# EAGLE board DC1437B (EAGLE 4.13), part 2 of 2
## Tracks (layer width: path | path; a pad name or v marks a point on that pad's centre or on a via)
+2.5V
  Bottom 0.203: 47.24,50.55 47.12,50.42 R9.2 47.75,50.42 | 45.85,49.28 C44.1 47.75,49.28 47.88,49.4
  Bottom 0.254: 47.24,51.94 U10.3
  Bottom 0.813: R13.1 30.8,38.67 30.86,38.74 R14.1 40.83,38.67 41.53,39.37 41.53,46.23 43.31,48.01 47.75,48.01 48.13,48.39 48.13,49.4 48.51,49.78
  pour Bottom (no thermals): 47.17,52.02 51.31,52.02 51.31,49.15 51.05,48.9 47.88,48.9 47.62,49.15 47.62,51 47.5,51.13 47.17,51.13
+3.3V  (via drill 0.38)
  Top 0.254: 47.11,39.11 47.12,39.12 | 51.98,44.61 51.94,44.58 51.94,44.07 51.99,44.11 | 51.94,33.66 51.99,33.61 51.99,33.19 51.94,33.15 51.98,33.11
  Top 0.305: U3.12 47.11,39.11 | 51.98,44.61 U3.48 | 51.99,44.11 U3.47 | 51.99,33.61 U3.26 | 51.98,33.11 U3.25 | U4.48 51.98,27.09 51.94,27.05 51.94,26.67 52.03,26.59 U4.47 | U4.12 47.11,21.59 47.12,21.59 | U4.25 51.98,15.59 51.94,15.62 51.94,16.13 51.99,16.09 U4.26
  Route2 0.61: v49.53,38.1 v49.53,39.62 | v49.53,20.57 v49.53,22.1
  Route3 0.61: v49.53,38.1 v49.53,39.62 | v49.53,20.57 v49.53,22.1
  Bottom 0.203: R29.2 53.21,16.89 v49.53,20.57 | R12.2 47.12,56.01 47.24,55.88 U10.10
  Bottom 0.61: TP3.1 43.31,57.28 47.37,57.28 | 47.37,57.28 47.5,57.28 | v49.53,20.57 v49.53,21.34 v49.53,22.1 v49.53,38.1 v49.53,38.86 v49.53,39.62 49.53,47.62 49.91,48.01 51.56,48.01 51.94,48.39 51.94,56.64 51.31,57.28 47.37,57.28
  Bottom 0.813: TP3.1 40.64,54.74 38.67,52.77 C5.1 38.74,51.44 38.74,49.34 R3.1 37.02,49.34 36.77,49.08 R16.1
  pour Top (no thermals): 52.07,46.23 52.07,31.5 46.99,31.5 46.99,46.23
  pour Top (isolate 0.254, no thermals): 46.99,28.7 46.99,13.97 52.07,13.97 52.07,28.7
  pour Bottom (no thermals): 47.8,54.41 47.8,57.51 47.32,57.51 47.04,57.51 47.04,55.68 47.04,55.17 47.14,55.07 47.19,55.02 47.19,54.41
+5V
  Bottom 0.813: TP5.1 31.05,52.77 C6.1 30.99,51.44 30.99,49.66 31.62,49.02 R15.1
AMP_EN
  Top 0.152: U2.C3 20.95,27.3 20.95,17.14 20.57,16.76 15.62,16.76 15.24,16.38 10.06,16.38 9.8,16.13 9.8,15.11 8.66,13.97 7.48,13.97 J6.4
ECCN  (via drill 0.25)
  Top 0.305: v33.91,30.1 R41.1 32.13,30.1 U2.E12
  Bottom 0.305: R4.2 35.62,17.34 35.31,17.65 35.31,29.34 34.67,29.97 34.04,29.97 v33.91,30.1
ENCP  (via drill 0.25)
  Top 0.305: v33.53,29.46 33.15,29.46 33.02,29.59 R41.2 32.13,29.59 U2.D12
  Bottom 0.305: R5.2 34.48,17.34 34.8,17.65 34.8,29.08 34.42,29.46 v33.53,29.46
EXT_REF
  Bottom 0.254: J4.5 13.99,11.32 13.97,11.3 TP1.1
GND  (via drill 0.3, 0.38, 0.81, 4.78)
  Top 0.127: U2.H10 29.21,33.91 29.84,33.27 29.84,33.02 | U2.H8 27,33.96 27.41,33.96 27.74,33.63 28.17,33.63 28.57,33.22 v28.57,31.75
  Top 0.152: v29.84,31.75 29.84,33.02
  Top 0.254: v35.94,45.59 34.93,45.59 | v35.94,45.59 36.83,45.59 | v35.94,45.59 35.94,46.48 | v35.94,44.32 v35.94,45.59 | 26.29,20.32 v27.3,20.32 | v27.3,20.32 28.19,20.32 | v27.3,20.32 27.3,21.34 | v27.3,20.32 27.3,19.3
  Top 0.305: U3.27 54.79,34.11 v55.12,33.91 | U3.23 44.53,33.61 | 44.53,33.61 44.45,33.53 | 44.53,33.61 44.53,33.99 44.65,34.11 U3.22 | U3.1 44.49,44.61 44.45,44.58 44.45,44.2 44.53,44.11 | U3.2 44.53,44.11 | 44.53,44.11 44.53,43.77 44.45,43.69 44.53,43.61 U3.3 | 44.54,27.09 U4.1 | 44.54,27.09 44.45,27.18 | 44.54,27.09 44.54,26.76 44.45,26.67 44.53,26.59 | U4.2 44.53,26.59 | 44.53,26.59 44.53,26.25 44.45,26.16 44.53,26.09 U4.3 | U4.46 54.53,26.09 54.61,26.16 | U4.23 44.49,16.09 44.45,16.13 44.45,16.51 44.53,16.59 U4.22 | U4.27 54.66,16.59 54.74,16.51 | U3.46 54.28,43.61 v54.74,44.07 | U3.36 54.61,38.61 54.61,39.12 53.21,39.12 | U4.36 53.34,21.09 53.34,21.08 54.74,21.08 54.74,21.59 53.21,21.59 | 25.53,31.62 v26.04,31.62 26.54,31.62 U2.F8 U2.F7 25.53,31.62
  Top 0.406: J1.6 v66.05,49.14 v66.04,49.15 | J1.12 67.95,46.74 67.94,46.74 v66.04,46.74 | J1.18 67.96,44.34 67.94,44.32 v66.04,44.32 | J1.24 67.97,41.94 67.94,41.91 v66.04,41.91 | J1.30 67.99,39.54 67.94,39.5 v66.04,39.5 | 68.07,37.09 68.07,37.08 | 68.07,37.09 J1.36 | v65.91,37.34 66.04,37.34 66.04,37.21 67.94,37.21 68.07,37.09 | J1.42 68.07,34.67 v66.04,34.67 | J1.48 68.12,32.34 68.2,32.26 v66.04,32.26 | J1.54 68.1,29.94 68.2,29.97 v66.04,29.97 | J1.60 67.99,24.26 v66.17,24.26 | J1.66 68.04,21.97 v66.17,21.97 | J1.72 68.05,19.56 v66.17,19.56 | J1.78 v66.17,17.14 | J1.84 v66.17,14.73 | J1.90 68.05,12.32 v66.17,12.32 | J1.96 68.04,9.91 v66.17,9.91 | U2.F1 U2.G2 | v15.11,31.24 13.95,31.24 C43.2 | C42.2 16.18,31.19 v15.88,31.24 | C39.2 v20.95,39.24 | J9.4 23.24,55.37 v23.24,52.07 | v14.73,52.07 J9.5
  Top 0.508: v12.83,57.28 12.95,57.28 13.33,57.79 | 13.33,57.79 16.13,57.79 16.13,52.96 15.88,52.71 13.59,52.71 13.33,52.96 13.33,57.79 | v25.27,57.4 25.27,57.53 25.02,57.79 24.77,57.79 | 24.77,57.79 21.84,57.79 21.84,57.66 21.97,57.53 21.97,52.96 22.22,52.71 24.51,52.71 24.77,52.96 24.77,57.79 | v0.76,39.24 0.64,39.12 0.64,38.74 | 0.64,38.74 0.64,35.69 0.89,35.94 5.46,35.94 5.71,36.2 5.71,38.35 5.33,38.74 0.64,38.74 | v0.89,30.73 0.64,30.73 0.64,30.1 | 0.64,30.1 0.64,27.05 0.89,27.3 5.46,27.3 5.71,27.56 5.71,29.84 5.46,30.1 0.64,30.1
  Top 0.61: U2.F1 v17.14,31.75 v16.64,31.24 16.18,31.19 v6.73,31.24 6.22,30.73 v0.89,30.73 | v17.78,34.93 U2.J1 | U2.H1 v17.78,34.93 | v18.41,34.29 U2.H1 | U2.H2 v18.41,34.29 | v19.05,33.66 U2.H2 | v19.05,33.66 U2.G2 v19.68,33.02 | U2.H2 v19.68,34.29 | v19.68,34.29 U2.H3 | v20.32,33.66 U2.H3 | v19.68,33.66 v19.68,34.29 | U2.G3 v20.32,33.66 | v19.68,33.02 U2.G3 | v19.68,33.02 v19.68,33.66 | v19.68,33.66 v19.68,34.29 | v20.32,34.93 U2.J3 | U2.H3 v20.32,34.93 | U2.G3 v20.32,32.38 | v20.32,32.38 U2.F3 v20.32,31.11 U2.E3 v20.32,29.84 | v20.32,29.84 U2.D3 v19.68,29.21 | v19.68,29.21 U2.D2 | U2.D2 v18.41,29.21 | v18.41,29.21 U2.D1 | U2.D1 v17.14,29.21 v17.14,28.57 | v17.14,28.57 v17.14,27.94 U2.C1 | v17.78,28.57 U2.C1 | v17.78,28.57 v17.14,28.57 | v18.41,28.57 v17.78,28.57 | v18.41,28.57 18.41,28.7 | v18.41,28.57 v18.41,27.94 | U2.C1 U2.C2 v19.05,28.57 | U2.D2 v19.05,28.57 | v19.05,28.57 v18.41,28.57 | v18.41,29.21 v18.41,28.57 | U2.D1 v17.78,28.57 | v17.14,34.93 v17.14,35.56 | v17.14,34.93 v17.14,34.29 U2.H1 | v17.78,34.93 v17.14,34.93 | U2.J1 v17.14,35.56 | U2.J1 v17.78,36.2 v17.14,36.2 | v17.14,35.56 v17.14,36.2 | v18.41,34.29 v17.78,34.93 | v19.68,34.29 v20.32,34.93 | U2.J3 v20.32,36.2 v20.95,36.2 | v19.05,33.66 v18.41,34.29 | v19.68,33.02 v20.32,32.38 | v20.32,29.84 v19.68,29.21 | U2.A1 v17.14,25.4 v17.14,24.77 v17.78,24.77 | U2.A1 v18.41,25.4 | v18.41,25.4 U2.A2 v19.05,24.77 v18.41,24.77 | v17.78,24.77 v18.41,24.77 | U2.A1 v17.78,24.77 | v18.41,25.4 v18.41,24.77 | U2.B3 v20.32,26.04 U2.A3 v20.32,24.77 | U2.A4 v21.59,24.77 v22.86,24.77 U2.A5 | U2.A4 v21.59,26.04 | v21.59,26.04 U2.B4 | U2.B4 v21.59,27.3 | v21.59,27.3 U2.C4 | U2.C4 v21.59,28.57 | v21.59,28.57 U2.D4 | U2.D4 v21.59,29.84 U2.E4
  Top 0.61: v25.4,26.04 U2.B7 v25.4,24.77 U2.A7 | v26.67,24.77 U2.A8 v26.67,26.04 U2.B8 | v24.13,24.77 U2.A6 v24.13,26.04 U2.B6 v24.13,27.3 U2.C6 | U2.A5 v22.86,26.04 U2.B5 | U2.B5 v22.86,27.3 | v22.86,27.3 U2.C5 | U2.C5 v22.86,28.57 | v22.86,28.57 U2.D5 U2.D4 | U2.G4 v21.59,33.66 U2.H4 v21.59,34.93 U2.J4 | U2.G5 v22.86,33.66 | v22.86,33.66 U2.H5 | v22.86,34.93 U2.H5 | v22.86,34.93 U2.J5 | U2.J5 v22.86,36.2 | v22.86,36.2 v22.22,36.2 | v22.22,36.2 v22.22,35.56 v22.22,34.93 v22.22,34.29 v22.22,33.66 v22.22,33.02 | v20.95,33.02 v20.95,33.66 v20.95,34.29 v20.95,34.93 v20.95,35.56 v20.95,36.2 | v20.95,36.2 v21.59,36.2 v22.22,36.2 | v22.86,36.2 v22.22,36.2 | U2.J5 v22.86,36.2 | U2.J3 U2.J5 | v20.32,34.93 U2.J3 | v20.32,34.93 v22.86,34.93 | v22.86,34.93 U2.H5 | U2.H3 U2.H5 | v20.32,33.66 U2.H3 | v20.32,33.66 v22.86,33.66 | U2.G5 v22.86,33.66 | U2.G3 U2.G5 | v31.75,27.3 U2.C12 v32.38,27.94 v32.38,27.3 | v31.75,27.3 U2.B12 | U2.B12 v31.75,26.04 | v31.75,26.04 U2.A12 | U2.A12 v31.75,24.77 v32.38,24.77 v32.38,25.4 | v32.38,26.04 v32.38,25.4 | v32.38,26.67 v32.38,26.04 | v32.38,27.3 v32.38,26.67 | v32.38,27.3 v31.75,27.3 | v32.38,26.67 U2.B12 | v32.38,26.04 v31.75,26.04 | v32.38,25.4 U2.A12 | U2.A11 v30.48,24.77 | v32.38,31.75 U2.F12 v31.11,31.75 U2.F11 | U2.F11 v29.84,31.75 | v29.84,31.75 U2.F10 | U2.F10 v28.57,31.75 | v28.57,31.75 U2.F9 | U2.F9 v27.3,31.75 U2.F8 | U2.F9 v27.94,31.11 U2.E9 v28.57,30.48 | U2.E10 v28.57,30.48 | v29.84,30.48 U2.E10 | v29.84,30.48 U2.E11 v30.48,31.11 U2.F11 | v29.84,30.48 v29.84,31.11 v29.84,31.75 | U2.E10 v29.21,31.11 U2.F10 | v28.57,30.48 v28.57,31.11 v28.57,31.75 | v31.75,34.93 v32.38,34.93 | v31.75,34.93 U2.H12 v32.38,34.29 v32.38,34.93
  Top 0.61: v32.38,34.93 v32.38,35.56 U2.J12 v31.75,34.93 | v22.22,24.77 v22.22,29.21 | v21.59,28.57 v22.86,28.57 | U2.C4 U2.C5 | v21.59,27.3 v22.86,27.3 | U2.B4 U2.B5 | v21.59,26.04 22.73,26.04 | U2.A4 U2.A5 | J5.5 3.68,29.21 v6.35,29.21 | J5.4 3.3,37.59 v6.35,37.59 | v16.76,57.4 16.76,52.45 v17.14,52.07 v17.14,36.2 | v20.95,36.2 20.95,51.82 v21.21,52.07 21.34,52.2 v21.34,52.83 v21.34,57.4 | v17.14,34.93 v6.35,34.93 5.97,35.31 v0.89,35.31
  Bottom 0.203: R24.1 v50.29,8.26 | SJ3.2 45.09,54.86 45.21,54.74 45.72,54.74 45.74,54.72 U10.7 45.74,53.45 46.18,53.01 46.18,52.96
  Bottom 0.254: R8.2 19.94,9.92 19.94,11.3 | 19.94,11.3 19.94,11.32 J2.5 19.95,11.32 19.94,11.3 | 18.54,11.3 18.57,11.33 | C19.2 19.94,11.3 | R10.1 44.51,51.88 45.21,52.58 45.72,52.58 46.18,52.96 46.48,53.21 v46.99,53.59 | v35.94,45.59 34.93,45.59 | v35.94,45.59 36.83,45.59 | v35.94,45.59 35.94,46.61 | v35.94,44.32 v35.94,45.59 | v27.3,20.32 26.42,20.32 | v27.3,20.32 28.19,20.32 | v27.3,20.32 27.3,19.3 | v27.3,20.32 27.3,21.34
  Bottom 0.406: J1.54 67.97,29.84 v66.04,29.97 | J1.48 67.99,32.26 v66.04,32.26 | J1.42 68,34.67 v66.04,34.67 | J1.36 68,37.21 v65.91,37.34 | J1.30 68.03,39.5 v66.04,39.5 | J1.24 68.04,41.91 v66.04,41.91 | J1.18 68.05,44.32 v66.04,44.32 | J1.12 v66.04,46.74 | J1.6 v66.04,49.15 | J1.96 68.04,9.91 v66.17,9.91 | J1.90 68.05,12.32 v66.17,12.32 | J1.84 v66.17,14.73 | J1.78 v66.17,17.14 | J1.72 68.05,19.56 v66.17,19.56 | J1.66 68.04,21.97 v66.17,21.97 | J1.60 67.99,24.26 v66.17,24.26 | v28.19,1.02 28.19,0.64 28.45,0.64 | 28.45,0.64 28.57,0.64 28.57,5.46 arc-90 28.83,5.71 31.37,5.71 31.37,0.64 28.45,0.64 | 40.01,0.89 v40.39,0.89 | 40.01,0.89 40.01,0.64 | 40.01,0.89 40.01,5.46 39.75,5.71 37.34,5.71 37.21,5.59 37.21,0.64 40.13,0.64
  Bottom 0.61: C2.1 35.56,6.73 35.81,6.48 v36.45,6.48 37.85,5.08 37.85,3.81 J7.4 38.61,5.71 v38.35,5.97 v37.34,6.98 v37.34,10.03 v38.1,10.03 38.35,10.03 v38.74,10.41 38.74,13.84 v37.72,13.84 | v32.38,13.84 C7.2 | v37.72,13.84 C3.2 | v32.38,13.84 v33.53,15.75 v33.53,17.27 v33.53,27.94 v32.38,27.94 | v37.72,13.84 v36.58,15.75 v36.58,17.27 v36.58,29.97 v35.05,31.5 v33.53,31.5 32.64,31.5 v32.38,31.75 | v32.38,13.84 31.37,13.84 v31.37,10.41 v32,10.03 v32.77,10.03 v32.77,6.98 29.97,4.19 J7.5 | 35.05,10.03 v35.43,10.03 v35.43,9.27 35.05,8.89 | 35.05,8.89 v35.05,8.76 35.05,10.03 | 35.05,8.89 v34.67,9.27 v34.67,10.03 35.05,10.03 | v36.58,7.24 v36.58,8 36.96,8 36.96,7.24 v36.58,7.24
  Bottom 0.813: C5.2 36.77,52.9 35.05,54.61 TP4.1 32.96,52.64 C6.2 | C45.2 47.18,53.4 v46.99,53.59
  other vias: 53.85,31.75 62.87,29.21 55.12,33.02 43.94,33.78 43.94,32.89 43.94,31.75 45.21,31.75 44.58,32.26 54.48,32.38 44.2,43.94 44.2,44.7 43.94,46.1 45.09,46.1 44.45,45.47 54.74,44.96 53.72,45.97 54.74,45.97 54.23,45.47 45.21,28.45 43.94,28.45 44.58,27.81 43.94,27.18 43.94,26.29 53.72,28.45 54.74,28.45 54.74,26.29 54.74,27.43 54.23,27.94 45.21,14.22 43.94,14.22 44.58,14.73 43.94,15.24 43.94,16.26 53.85,14.22 55.12,14.22 54.48,14.86 55.12,15.49 55.12,16.38 32.77,14.48 37.34,14.48 36.96,15.11 33.15,15.11 33.53,16.51 36.58,16.51 18.41,32.38 14.35,31.24 13.59,31.24 12.83,31.24 12.06,31.24 11.3,31.24 10.54,31.24 9.78,31.24 9.02,31.24 8.26,31.24 7.49,31.24 6.35,30.61 16.26,34.93 15.49,34.93 14.73,34.93 13.97,34.93 13.21,34.93 12.45,34.93 11.68,34.93 10.92,34.93 10.16,34.93 9.4,34.93 8.64,34.93 7.87,34.93 7.11,34.93 6.73,35.56 15.88,35.56 7.11,36.2 15.11,35.56 14.35,35.56 13.59,35.56 12.83,35.56 12.06,35.56 11.3,35.56 10.54,35.56 9.78,35.56 9.02,35.56 8.26,35.56 7.49,35.56 7.87,36.2 16.26,30.61 15.49,30.61 14.73,30.61 13.97,30.61 13.21,30.61 12.45,30.61 11.68,30.61 10.92,30.61 10.16,30.61 9.4,30.61 8.64,30.61 7.87,30.61 7.11,30.61 5.46,30.73 7.49,29.97 22.22,28.57 22.22,27.94 22.22,27.3 22.22,26.67 22.22,26.04 22.22,25.4 20.95,36.96 20.95,37.72 20.95,38.48 20.95,40.01 20.95,40.77 20.95,41.53 20.95,42.29 20.95,43.05 20.95,43.82 20.95,44.58 20.95,45.34 20.95,46.1 20.95,46.86 20.95,47.62 20.95,48.39 20.95,49.15 20.95,49.91 20.95,50.67 21.84,52.32 24,52.07 17.14,36.96 17.14,37.72 17.14,38.48 17.14,39.24 17.14,40.01 17.14,40.77 17.14,41.53 17.14,42.29 17.14,43.05 17.14,43.82 17.14,44.58 17.14,45.34 17.14,46.1 17.14,46.86 17.14,47.62 17.14,48.39 17.14,49.15 17.14,49.91 17.14,50.67 16.38,52.2 13.97,52.07 21.59,37.34 21.59,38.1 21.59,38.86 21.59,39.62 21.59,40.39 21.59,41.15 21.59,41.91 21.59,42.67 21.59,43.43 21.59,44.2 21.59,44.96 21.59,45.72 21.59,46.48 21.59,47.24 21.59,48.01 21.59,48.77 21.59,49.53 21.59,50.29 21.59,51.05 22.35,51.05 22.48,52.07 16.51,37.34 16.51,38.1 16.51,36.58 16.51,38.86 16.51,39.62 16.51,40.39 16.51,41.15 16.51,41.91 16.51,42.67 16.51,43.43 16.51,44.2 16.51,44.96 16.51,45.72 16.51,46.48 16.51,47.24 16.51,48.01 16.51,48.77 16.51,49.53 16.51,50.29 16.51,51.05 15.75,51.05 15.49,52.07 16.51,35.81 15.62,36.2 15.88,36.96 14.73,36.2 15.24,36.83 15.88,37.72 15.24,37.47 14.48,36.83 13.97,36.2 33.53,18.03 33.53,18.8 33.53,19.56 36.58,18.03 36.58,18.8 36.58,19.56 36.58,20.95 33.53,20.95 33.53,22.35 36.58,22.35 33.53,23.75 36.58,23.75 36.58,24.51 36.58,25.91 33.53,25.65 33.02,25.15 33.53,26.42 33.53,27.18 36.58,26.54 36.58,27.3 36.58,27.94 36.58,29.21 36.07,30.48 35.56,30.99 34.29,31.5 33.02,32 32.89,31.11 33.91,32.13 34.67,32.13 35.43,32.13 35.94,31.62 36.45,31.11 36.96,30.61 37.21,29.97 37.21,29.21 37.21,27.69 37.21,26.92 37.21,26.16 37.85,27.3 37.85,26.54 37.85,27.94 37.85,25.91 33.02,27.56 33.02,26.8 33.02,26.04 46.99,52.83 45.72,53.59 45.72,52.83 46.36,53.21 47.62,53.21 48.26,53.59 48.26,52.83 31.37,13.46 31.37,12.7 31.37,11.94 31.37,11.18 32.77,9.27 32.77,8.51 32.77,7.75 32.26,6.48 38.74,13.46 38.74,12.7 38.74,11.94 38.74,11.18 37.34,9.27 37.34,8.51 37.34,7.75 38.1,6.86 32,8.89 32,8.13 32,7.37 31.5,6.86 31.5,9.4 16.76,56.64 16.76,55.88 16.76,55.12 16.76,54.36 16.76,53.59 16.76,52.83 21.34,56.64 21.34,55.88 21.34,55.12 21.34,54.36 21.34,53.59 1.65,35.31 2.41,35.31 3.17,35.31 3.94,35.31 4.7,35.31 5.46,35.31 1.65,30.73 2.41,30.73 3.17,30.73 3.94,30.73 4.7,30.73 8.26,29.97 36.45,1.02 36.45,1.78 36.45,2.54 36.45,3.3 36.45,4.06 36.45,4.83 32.26,1.02 32.26,1.78 32.26,2.54 32.26,3.3 32.26,4.06 32.26,4.83 31.62,5.21 40.39,1.65 40.39,2.41 40.39,3.17 40.39,3.94 40.39,4.7 40.39,5.46 39.88,5.97 39.12,5.97 28.19,1.78 28.19,2.54 28.19,3.3 28.19,4.06 28.19,4.83 28.19,5.59 28.7,6.1 29.46,6.1 30.23,6.1 30.99,6.1 1.52,39.24 2.29,39.24 3.05,39.24 3.81,39.24 4.57,39.24 5.33,39.24 6.35,36.83 6.35,38.35 5.97,38.99 0.89,26.8 1.65,26.8 2.41,26.8 3.17,26.8 3.94,26.8 4.7,26.8 5.46,26.8 6.1,27.05 6.35,27.69 6.35,28.45 13.33,52.2 12.83,52.71 12.83,53.47 12.83,54.23 12.83,54.99 12.83,55.75 12.83,56.52 24.77,52.32 25.27,52.83 25.27,53.59 25.27,54.36 25.27,55.12 25.27,55.88 25.27,56.64 58.42,3.81 5.71,3.81 5.71,54.61 58.42,54.61 54.86,38.86 55.88,38.86 56.9,38.86 57.91,38.86 59.05,39.24 60.2,39.5 61.34,39.5 62.48,39.5 63.63,39.5 64.77,39.5 60.96,36.96 61.98,37.34 62.99,36.96 64.01,37.34 65.02,36.96 65.02,34.54 64.14,34.93 63.12,34.54 62.1,34.93 61.21,34.54 59.31,35.94 60.33,35.05 57.79,34.93 58.67,34.04 59.56,33.15 60.45,32.38 61.72,32.51 62.87,32.13 64.01,32.51 65.02,32.13 59.18,41.66 60.2,42.16 61.09,41.66 62.23,42.16 63.25,41.66 64.26,42.16 65.15,41.66 54.74,21.34 55.88,21.34 57.15,21.34 58.42,21.34 59.82,21.34 61.09,21.34 65.28,17.4 64.9,22.1 59.94,19.3 61.09,18.29 62.1,17.27 63.12,16.26 64.39,15.11 65.02,10.03 60.45,10.03 61.98,10.03 64.64,12.32 59.82,46.48 60.83,46.99 61.85,46.48 62.87,46.99 64.01,46.48 65.15,46.99 59.44,44.07 60.83,44.58 62.1,44.07 63.37,44.58 64.64,44.07 62.23,27.94 62.99,26.67 64.14,30.1 60.96,29.84 60.96,26.67 59.44,28.32 57.79,29.84 57.79,26.67 56.52,33.02 55.88,31.11 53.98,29.84 52.2,30.1 50.55,30.73 48.51,30.73 48.51,29.46 50.55,29.46 46.99,30.1 55.88,28.57 55.88,26.67 43.31,21.46 42.04,21.08 40.64,21.46 39.37,21.08 38.1,21.59 43.05,19.3 43.05,17.27 41.28,19.3 39.5,19.3 37.85,19.3 38.61,18.16 40.39,18.16 42.16,18.16 37.59,17.14 39.37,17.14 41.28,17.14 38.35,15.88 40.39,15.88 42.29,15.88 39.37,14.61 41.28,14.61 42.16,13.08 40.26,13.08 41.28,11.43 44.07,13.08 45.97,13.08 47.88,13.08 50.29,13.08 48.9,11.43 46.99,11.43 45.09,11.43 43.18,11.43 40.26,9.53 42.16,9.53 44.07,9.53 45.97,9.53 48.01,9.53 50.29,9.53 41.28,7.62 39.37,7.62 43.18,7.62 45.09,7.62 46.99,7.62 48.9,7.62 42.16,5.71 44.07,5.71 45.97,5.71 47.88,5.71 50.29,5.71 43.18,3.81 45.09,3.81 46.99,3.81 48.9,3.81 50.8,3.81 41.4,3.81 42.16,1.91 44.07,1.91 45.97,1.91 47.88,1.91 49.78,1.91 43.18,0.76 45.09,0.76 46.99,0.76 48.9,0.76 50.8,0.76 52.71,0.76 54.61,0.76 56.52,0.76 52.71,5.71 62.23,0.76 62.23,2.54 62.23,4.45 62.23,6.35 62.23,7.62 55.88,6.98 53.98,6.98 13.33,38.74 13.97,38.1 12.7,38.1 13.33,37.47 12.06,37.47 11.43,38.1 10.79,37.47 10.16,38.1 8.89,38.1 7.62,38.1 8.26,37.47 9.53,37.47 8.89,36.83 10.16,36.83 11.43,36.83 12.7,36.83 9.53,36.32 10.79,36.32 12.06,36.32 13.21,36.32 13.72,36.83 14.22,37.47 14.61,38.74 15.88,38.74 15.11,38.1 15.88,40.64 13.33,40.64 10.79,40.64 8.26,40.64 5.71,40.64 3.17,40.64 0.76,40.64 14.61,41.91 12.06,41.91 9.53,41.91 6.98,41.91 4.45,41.91 1.91,41.91 6.98,39.37 9.53,39.37 12.06,39.37 15.88,43.18 13.33,43.18 10.79,43.18 8.26,43.18 5.71,43.18 3.17,43.18 0.76,43.18 14.61,44.45 12.06,44.45 9.53,44.45 6.98,44.45 4.45,44.45 1.91,44.45 15.88,45.59 13.33,45.72 10.79,45.72 8.26,45.72 5.71,45.72 3.17,45.72 0.76,45.72 1.91,46.99 4.45,46.99 7.11,46.99 9.53,46.99 12.06,46.99 14.61,46.99 13.33,48.26 15.88,48.26 10.79,48.26 8.26,48.26 5.71,48.26 3.17,48.26 0.76,48.26 1.91,49.53 4.45,49.53 6.98,49.53 9.53,49.53 12.06,49.53 14.61,49.53 13.33,50.8 10.79,50.8 8.26,50.8 5.71,50.8 3.17,50.8 0.76,50.8 1.91,52.07 0.76,53.34 1.91,54.61 0.76,55.88 1.91,57.15 9.53,52.07 11.94,52.07 8.89,57.15 0.76,57.66 11.43,57.15 15.24,29.84 13.97,29.84 12.7,29.84 11.43,29.84 10.16,29.84 15.24,28.57 13.97,28.57 12.7,28.57 11.43,28.57 10.16,28.57 8.89,28.57 7.62,28.57 9.02,29.84 15.24,27.3 12.7,27.3 10.16,27.3 7.62,27.3 13.97,26.04 11.43,26.04 8.89,26.04 6.48,26.04 15.24,24.77 12.7,24.77 10.16,24.77 7.62,24.77 5.08,24.77 2.54,24.77 13.97,23.5 11.43,23.5 8.89,23.5 6.35,23.5 3.81,23.5 1.27,23.5 2.54,22.22 5.08,22.22 7.62,22.22 10.16,22.22 12.7,22.22 15.24,22.22 13.97,20.95 11.43,20.95 8.89,20.95 6.35,20.95 3.81,20.95 1.27,20.95 2.54,19.68 5.08,19.68 7.62,19.68 10.16,19.68 12.7,19.68 15.24,19.68 13.97,18.41 11.43,18.41 8.89,18.41 6.35,18.41 3.81,18.41 1.27,18.41 5.08,17.14 2.54,17.14 1.27,15.88 2.54,14.61 1.27,13.33 2.54,12.06 1.27,10.79 2.54,9.53 1.27,8.26 2.54,6.98 1.27,5.71 2.54,4.45 1.27,3.17 5.08,9.53 3.81,8.26 5.08,6.98 6.35,8.26 7.62,9.53 7.62,6.98 8.89,8.26 10.16,9.53 10.16,6.98 11.43,8.26 12.7,9.53 12.7,6.98 11.43,10.79 8.89,10.79 10.16,12.06 8.89,13.33 11.43,13.33 12.7,12.06 10.16,14.61 11.43,15.75 8.89,15.75 12.7,14.61 11.43,5.71 10.16,4.45 8.89,5.71 8.89,3.17 11.43,3.17 10.16,1.91 8.89,0.76 11.43,0.76 6.35,0.76 3.81,0.76 13.97,0.76 16.51,0.76 19.05,0.76 16.51,3.17 16.51,5.71 16.51,8.26 15.24,6.98 17.78,6.98 17.78,9.53 15.24,9.53 16.51,10.16 19.05,8.26 19.05,10.16 19.05,5.71 20.32,6.98 22.86,6.98 21.59,8.26 21.59,5.71 22.86,4.45 22.86,1.91 21.59,3.17 21.59,0.76 24.13,0.76 26.67,0.76 25.4,1.91 24.13,3.17 26.67,3.17 25.4,4.45 26.67,5.71 24.13,5.71 25.4,6.98 24.13,8.26 22.86,9.53 25.4,9.53 26.67,8.26 25.4,11.56 24.13,10.41 27.94,9.53 30.48,9.53 29.08,8.26 30.48,7.11 27.94,6.98 30.48,12.06 30.61,14.61 31.75,15.88 31.75,18.41 32.77,17.14 31.24,17.14 32.77,19.3 40.26,26.04 42.55,26.04 41.28,27.3 42.55,28.57 40.01,28.57 41.28,29.84 43.82,29.84 42.55,31.11 40.01,31.11 41.28,32.38 42.55,33.66 40.01,33.66 38.74,32.26 38.74,29.84 37.47,33.66 36.2,32.38 37.47,31.11 34.93,33.66 36.2,34.93 33.66,34.93 34.93,36.07 33.4,32.64 23.5,43.18 23.5,40.64 22.22,41.91 24.77,41.91 22.22,44.45 24.77,44.45 26.04,43.18 27.3,44.45 26.04,45.72 23.5,45.72 24.77,46.99 22.22,46.99 23.5,48.26 22.22,49.53 24.77,49.53 26.04,48.26 27.3,46.99 28.57,45.72 28.57,48.26 27.3,49.53 29.84,49.53 28.57,50.8 26.04,50.8 23.5,50.8 27.3,52.07 29.84,52.07 29.84,46.99 31.11,45.72 29.21,44.45 32.26,44.45 33.02,46.99 30.48,44.45 30.99,48.26 37.47,44.32 36.96,47.5 34.67,44.32 40.01,44.32 40.01,46.99 40.01,49.53 40.01,52.07 41.28,50.8 41.28,48.26 42.55,49.53 43.82,50.8 42.55,52.07 43.82,53.34 43.82,55.88 40.01,57.15 37.47,57.15 34.93,57.15 32.38,57.15 29.84,57.15 27.3,57.15 32.38,54.61 31.11,55.88 37.47,54.61 53.98,50.8 56.52,50.8 59.05,50.8 61.6,50.8 64.14,50.8 62.87,49.53 65.41,49.53 60.33,49.53 57.79,49.53 55.25,49.53 52.83,49.53 53.98,48.26 56.52,48.26 57.79,46.99 56.52,45.72 55.25,46.99 52.71,46.99 50.42,46.99 47.62,46.99 42.8,44.07 42.8,45.85 44.58,46.99 55.25,52.07 52.83,52.07 60.33,52.07 62.74,52.07 61.6,53.34 62.74,54.61 61.6,55.37 55.25,57.15 52.71,57.15 17.78,22.22 19.05,20.95 17.78,19.68 19.05,18.41 16.64,17.91 23.75,21.46 24.13,18.41 25.78,19.18 25.53,22.22 25.4,17.14 26.67,18.41 29.21,18.41 28.07,19.3 27.94,17.14 26.16,21.08 21.59,20.95 21.59,18.41 21.59,23.11 20.32,22.22 20.32,19.68 20.32,18.29 25.15,14.61 25.15,12.95 23.62,16.38 24,23.11
  pour Top (no thermals): 54.48,34.16 54.48,32.77 54.36,32.64 52.83,32.64 52.83,31.5 55.37,31.5 55.37,34.16
  pour Top (no thermals): 44.58,34.16 44.58,32.64 44.7,32.51 46.23,32.51 46.23,31.5 43.82,31.5 43.69,31.62 43.69,34.16
  pour Top (no thermals): 46.23,46.36 46.23,45.21 44.83,45.21 44.58,44.96 44.58,43.56 43.69,43.56 43.69,46.23 43.82,46.36
  pour Top (no thermals): 52.83,46.23 52.83,45.21 54.36,45.21 54.48,45.09 54.48,43.56 54.99,44.07 54.99,46.1 54.86,46.23
  pour Top (no thermals): 54.48,16.64 54.48,15.24 54.36,15.11 52.83,15.11 52.83,13.97 55.37,13.97 55.37,16.64
  pour Top (no thermals): 44.58,16.64 44.58,15.11 44.7,14.99 46.23,14.99 46.23,13.97 43.82,13.97 43.69,14.1 43.69,16.64
  pour Top (no thermals): 52.83,28.7 52.83,27.69 54.36,27.69 54.48,27.56 54.48,26.04 54.99,26.04 54.99,28.57 54.86,28.7
  pour Top (no thermals): 46.23,28.7 46.23,27.56 44.83,27.56 44.58,27.3 44.58,25.91 43.69,25.91 43.69,28.57 43.82,28.7
  pour Route3 (isolate 0.254): 0.38,58.04 63.12,58.04 63.12,51.44 68.58,51.44 68.58,7.75 63.12,7.75 63.12,0.38 0.38,0.38
  pour Top (no thermals): 27.94,0 27.94,5.71 arc-90 28.57,6.35 31.11,6.35 31.62,5.84 37.85,5.84 38.23,6.22 40.13,6.22 arc-90 40.64,5.71 40.64,0
  pour Bottom (no thermals): 0,39.5 5.46,39.5 arc-90 6.6,38.35 6.6,36.83 5.84,36.07 5.71,35.94 5.71,30.23 6.6,29.34 6.6,27.56 arc-90 5.59,26.54 5.46,26.54 0,26.54
  pour Bottom (no thermals): 12.57,58.42 12.57,52.58 arc90 13.33,51.82 24.64,51.82 arc90 25.53,52.71 25.53,58.42
  pour Bottom (isolate 0.254, rank 2): 68.58,51.56 64.14,51.56 arc-90 63.25,52.45 63.25,58.17 0.25,58.17 0.25,0.25 63.25,0.25 63.25,6.73 arc-90 64.01,7.49 68.58,7.49
  pour Top (isolate 0.254, rank 2): 0.25,58.17 63.25,58.17 63.25,52.32 arc90 64.01,51.56 68.71,51.56 68.71,7.49 64.14,7.49 arc81 63.25,6.73 63.25,0.25 0.25,0.25
  pour Route2 (isolate 0.381): 0.25,58.17 63.25,58.17 63.25,52.32 arc90 64.01,51.56 68.58,51.56 68.58,7.62 64.14,7.62 arc90 63.25,6.73 63.25,0.25 0.25,0.25
  pour Bottom (no thermals): 44.07,1.91 50.29,1.91 50.29,5.71 44.07,5.71
GROM
  Bottom 0.203: U1.4 59.9,16.6 59.82,16.51 | U1.3 59.25,16.58 59.18,16.51 | U1.2 58.6,16.57 58.55,16.51 | U1.1 57.95,16.68 57.91,16.64 | 56.1,13.94 57.5,13.94 57.91,14.35
  Bottom 0.254: J8.2 54.74,10.29 54.23,10.79 54.23,12.83 54.48,13.08 55.25,13.08 | 55.25,13.08 C27.2 | 55.25,13.08 55.75,13.59
  Bottom 0.406: J1.85 56.1,13.94 55.75,13.59
  pour Bottom: 57.53,16.89 60.33,16.89 60.33,13.84 57.53,13.84
LO
  Top 0.508: U2.J2 L5.2
MIX_EN
  Top 0.152: U2.F4 20.95,31.11 20.95,28.83 20.7,28.57 19.94,28.57 19.68,28.32 19.68,17.4 19.43,17.14 15.49,17.14 15.11,16.76 9.73,16.76 9.47,16.51 9.47,15.24 8.59,14.35 5.86,14.35 J6.3
MODE
  Top 0.152: J2.4 22.61,13.33 22.99,13.72 22.99,23.37 23.5,23.88 24.26,23.88 24.77,24.38 24.77,27.3 U2.C7
  Bottom 0.254: J2.4 21.95,13.31 19.98,13.31 J2.3
N$1
  Bottom 0.406: T2.4 33.78,8.89 34.29,8.38 C1.2
N$2
  Bottom 0.406: T2.5 36.32,9.02 35.56,8.26 C2.2
N$3
  Bottom 0.813: 35.05,11.3 35.05,14.22
  pour Bottom (no thermals): 34.54,14.61 34.54,13.84 34.8,13.59 34.8,11.81 34.67,11.68 32,11.68 32,10.79 38.1,10.79 38.1,11.68 35.43,11.68 35.31,11.81 35.31,13.59 35.56,13.84 35.56,14.61
N$4
  Bottom 0.406: J7.1 34.42,3.05 34.29,3.17 C1.1
N$5  (via drill 0.25)
  Top 0.127: v23.5,38.61 23.5,39.24 23.88,39.62 24,39.62 27.81,43.43 42.37,43.43 42.67,43.13 43.49,43.13
  Top 0.152: R17.1 43.49,43.13 43.5,43.11 U3.4 | v24.77,29.84 U2.D6
  Route2 0.127: v24.77,29.84 24.77,30.35 24,31.11 24,32 23.5,32.51 v23.5,38.61
N$6
  Bottom 0.305: R5.1 34.54,16.32 34.54,15.49 C4.2 33.66,14.57 33.66,14.35 R2.1 33.78,14.29 T2.3
N$7
  Bottom 0.305: R4.1 35.56,16.32 35.56,15.49 C4.1 36.32,14.7 36.32,14.29 | 36.32,14.29 36.32,14.22 | 36.32,14.29 R1.1 | T2.1 36.32,14.29
N$8
  Top 0.152: J6.2 6.84,16.9 7.34,17.4 R36.1
N$9
  Top 0.406: 13.97,32.97 13.97,32.98 C43.1 | 14.53,32.97 14.62,32.98 L1.1
  Top 0.508: C43.1 9.69,32.98 9.65,33.02 C37.1 C37.2 | C37.2 8.76,33.02 | J5.1 C37.2 | 13.97,32.97 14.53,32.97
N$10
  Bottom 0.203: U10.8 46.24,56 46.23,56.01 R12.1 46.29,56.2 46.23,56.26 SJ3.1
N$11
  Bottom 0.254: R7.1 23.74,11.3 21.97,11.3 | 21.97,11.3 21.97,11.32 J2.6 | R8.1 21.97,9.92 21.97,11.3
N$12  (via drill 0.25)
  Top 0.152: U2.F5 22.73,31.75 v22.22,32.26
  Bottom 0.152: R28.1 22.48,32.26 v22.22,32.26
N$13
  Top 0.305: C39.1 19.05,39.24
  Top 0.508: L5.1 19.05,39.24 J9.1
N$14
  Top 0.152: U3.44 54.93,42.61 60.07,47.75 67.82,47.75 68.07,47.5 | 68.07,47.5 | 68.07,47.5 J1.10
N$15
  Bottom 0.254: R6.2 21.7,17.03 21.95,16.78 J2.2 21.95,15.35 21.97,15.37 21.98,15.36 R11.2
N$16
  Top 0.152: U4.45 55.56,25.59 55.75,25.78 67.69,25.78 67.94,26.04 68.04,25.94 J1.56
N$17
  Top 0.152: U3.45 54.8,43.11 59.82,48.13 67.56,48.13 67.77,48.34 J1.8
N$18
  Top 0.152: U3.30 58.11,35.61 60.45,33.27 67.94,33.27 J1.46
N$19
  Top 0.152: 67.69,35.69 67.84,35.54 J1.40 67.96,35.54 67.82,35.69 60.58,35.69 59.65,36.61 U3.32
N$20
  Top 0.152: 68.07,36.45 | 68.07,36.45 J1.38 68.07,36.32 67.94,36.2 60.71,36.2 59.79,37.11 U3.33 | 68.07,36.45 67.82,36.2
N$21
  Top 0.152: 68.07,37.97 67.94,38.1 | U3.34 59.08,37.61 59.56,38.1 67.31,38.1 67.44,37.97 68.07,37.97 | 68.07,37.97 J1.34
N$22
  Top 0.152: 67.69,38.61 67.94,38.86 J1.32 67.94,38.61 59.44,38.61 58.94,38.11 U3.35
N$23
  Top 0.152: U3.38 58.41,39.61 59.31,40.51 67.94,40.51 68.07,40.39 68.07,40.38 J1.28
N$24
  Top 0.152: U3.39 58.27,40.11 59.05,40.89 67.82,40.89 J1.26 | J1.26 | J1.26
N$25
  Top 0.152: U3.40 57.12,40.61 59.44,42.93 67.44,42.93 67.82,42.55 68.01,42.74 J1.22
N$26
  Top 0.152: U3.41 56.99,41.11 59.18,43.31 67.69,43.31 67.94,43.56 67.97,43.54 J1.20
N$27
  Top 0.152: U3.42 55.84,41.61 59.56,45.34 67.82,45.34 68.07,45.09 | 68.07,45.09 | 68.07,45.09 J1.16
N$28
  Top 0.152: U3.43 55.7,42.11 59.31,45.72 67.44,45.72 67.69,45.97 67.72,45.94 J1.14
N$29
  Top 0.152: U4.44 55.69,25.09 55.88,25.27 67.94,25.27 68.07,25.4 | 68.07,25.4 | 68.07,25.4 J1.58
N$30
  Bottom 0.203: U10.5 46.24,50.53 46.36,50.42 | 46.36,50.42 R9.1 | 46.36,50.42 R10.2
N$31
  Top 0.152: U4.43 63.55,24.59 64.77,23.37 67.69,23.37 67.86,23.54 J1.62
N$32
  Top 0.152: U4.42 63.29,24.09 64.52,22.86 68.2,22.86 J1.64
N$33
  Top 0.152: U3.31 58.25,36.11 60.58,33.78 67.82,33.78 67.98,33.94 J1.44
N$34
  Top 0.152: U4.41 62.39,23.59 65.02,20.95 68.2,20.95 68.33,21.08 68.27,21.14 J1.68
N$35
  Top 0.152: U4.40 62.13,23.09 64.77,20.45 67.56,20.45 67.69,20.32 67.71,20.34 J1.70
N$36
  Bottom 0.152: U10.6 45.29,51.76 44.96,51.44 44.96,49.28 C44.2
N$37
  Top 0.152: U4.39 61.49,22.59 65.41,18.67 67.94,18.67 68.07,18.79 | 68.07,18.79 68.2,18.92 | 68.07,18.79 J1.74
N$38
  Top 0.152: U4.38 61.35,22.09 65.28,18.16 67.82,18.16 68.04,17.94 J1.76
N$39
  Top 0.152: U4.35 60.95,20.59 65.28,16.26 68.2,16.26 68.28,16.34 | 68.28,16.34 68.45,16.51 | 68.28,16.34 J1.80
N$40
  Top 0.152: U4.34 60.56,20.09 64.9,15.75 67.94,15.75 68.07,15.62 J1.82
N$41
  Top 0.152: U4.33 58.52,19.59 64.26,13.84 68.33,13.84 68.23,13.94 J1.86
N$42
  Top 0.152: U4.32 58.13,19.09 63.88,13.33 68.2,13.33 68.33,13.21 68.26,13.14 J1.88
N$43
  Top 0.152: U4.31 57.36,18.59 64.52,11.43 68.2,11.43 68.09,11.54 J1.92
N$44
  Top 0.152: U4.30 57.23,18.09 64.39,10.92 67.94,10.92 68.07,10.79 J1.94
N$45
  Top 0.152: U4.29 56.33,17.59 64.9,9.02 67.82,9.02 67.94,9.14 J1.98
N$46
  Top 0.152: U4.28 56.19,17.09 64.77,8.51 68.07,8.51 J1.100
N$47
  Bottom 0.254: R27.1 56.45,12.89 56.77,13.21 58.29,13.21 58.6,12.9 U1.7 | U1.7 | U1.7 58.6,10.29 J8.1
N$48
  Top 0.508: 14.68,32.97 15.47,32.97
N$49  (via drill 0.25)
  Top 0.152: v22.22,31.11 U2.E5
  Bottom 0.152: R28.2 22.61,31.11 v22.22,31.11
N$50
  Top 0.152: U3.29 56.58,35.11 60.33,31.37 67.82,31.37 68.07,31.62 | 68.07,31.62 | 68.07,31.62 J1.50
N$51
  Top 0.152: U3.28 56.45,34.61 60.2,30.86 68.2,30.86 68.32,30.74 | 68.32,30.74 68.33,30.73 | 68.32,30.74 J1.52
N$60
  Top 0.127: 44.19,34.61 37.65,34.61 35.56,36.7 30.23,36.7 29.97,36.45 | U2.J11 29.97,36.07
  Top 0.152: R30.2 44.17,34.6 44.19,34.61 U3.21 | 29.97,36.07 29.97,36.45
N$63
  Top 0.127: 44.07,35.05 37.72,35.05 35.69,37.08 29.97,37.08 29.59,36.7 29.59,36.07 29.21,35.69
  Top 0.152: R30.1 44.17,35.08 | U3.20 44.21,35.11 R30.1 | 44.07,35.05 44.12,35.1 R30.1 | U2.J10 29.21,35.69
N$65  (via drill 0.25)
  Top 0.127: v24.13,39.12 28.07,43.05 42.14,43.05 42.6,42.6 43.41,42.6 R17.2
  Top 0.152: R17.2 43.43,42.6 43.45,42.61 U3.5 | U2.E6 v24.77,31.11
  Route2 0.127: v24.77,31.11 24.77,31.75 23.88,32.64 23.88,38.23 24.13,38.48 v24.13,39.12
N$66  (via drill 0.25)
  Top 0.127: v24.77,38.48 24.77,39.37 25.02,39.62 25.27,39.62 28.32,42.67 | 41.78,42.67 42.42,42.04 44.32,42.04 | U2.F6 24.13,31.88 24.38,32 24.64,32 25.02,32.38 v26.04,32.38
  Top 0.152: U3.6 44.27,42.11 44.25,42.09 44.22,42.11 R18.1 44.25,42.11 44.32,42.04 | 28.32,42.67 41.78,42.67
  Route2 0.127: 24.77,34.42 v24.77,38.48
  Route2 0.152: v26.04,32.38 24.64,32.38 24.26,32.77 24.26,33.91 24.77,34.42
N$68  (via drill 0.25)
  Top 0.127: v25.27,39.12 28.45,42.29 41.53,42.29 42.29,41.53 44.07,41.53
  Top 0.152: 44.2,41.63 44.17,41.66 | 44.2,41.63 R18.2 44.15,41.61 44.07,41.53 | U3.7 44.22,41.61 44.2,41.63 | U2.G6 v24.77,33.66
  Route2 0.127: 25.4,34.29 25.4,38.99 v25.27,39.12
  Route2 0.152: v24.77,33.66 25.4,34.29
N$69  (via drill 0.25)
  Top 0.127: U2.D10 29.72,28.7 38.61,28.7 39.37,27.94 v39.37,26.16 | R34.1 44.2,22.61 44.07,22.61 43.94,22.48 39.75,22.48 v39.62,22.61
  Top 0.152: R34.1 | R34.1 U4.10 | R34.1 44.17,22.61
  Route2 0.127: v39.37,26.16 39.37,22.86 v39.62,22.61
N$70
  Top 0.127: 44.2,40.11 40.77,40.13 40.28,40.62 29.18,40.62 25.15,36.58 25.15,36.32 24.89,36.07 24.89,34.8
  Top 0.152: R20.1 44.2,40.11 44.22,40.08 44.25,40.11 U3.10 | U2.H7 24.89,34.8
N$71
  Top 0.127: R35.1 42.95,20.6 42.8,20.45 31.88,20.45 31.5,20.07 29.84,20.07 29.59,20.32 29.59,24.64 29.72,24.77 29.72,25.91 29.46,26.16 29.46,26.42 U2.B10
  Top 0.152: R35.1 43.46,20.6 43.47,20.59 U4.14
N$73  (via drill 0.25)
  Top 0.127: U2.D8 25.91,28.45 25.91,24.26 v25.53,23.88 | v31.75,23.88 32.51,23.88 34.04,25.4 43.18,25.4 43.31,25.53 43.43,25.53 R31.1
  Top 0.152: R31.1 43.46,25.6 43.48,25.59 U4.4
  Route2 0.127: v25.53,23.88 v31.75,23.88
N$74
  Top 0.127: R21.1 39.6,38.12 38.1,39.62 29.34,39.62 25.91,36.2 25.91,33.4 26.04,33.27 26.42,33.27 U2.G8
  Top 0.152: R21.1 43.46,38.1 43.47,38.11 U3.14
N$75
  Top 0.127: U2.A10 29.21,20.07 29.59,19.68 31.75,19.68 32.13,20.07 43.43,20.07
  Top 0.152: 43.38,20.09 43.36,20.12 | 43.38,20.09 R35.2 43.43,20.07 | U4.15 43.39,20.09 43.38,20.09
N$76
  Top 0.127: 44.2,37.08 44.07,36.96 38.48,36.96 36.83,38.61 29.34,38.61 27.56,36.83 27.56,36.32 U2.J8
  Top 0.152: U3.16 44.15,37.11 R22.1 44.2,37.08
N$77
  Top 0.127: 44.16,36.61 38.45,36.61 36.7,38.35 29.46,38.35 27.94,36.83 U2.J9
  Top 0.152: R22.2 44.15,36.6 44.16,36.61 U3.17
N$78
  Top 0.127: 43.43,36.07 38.1,36.07 36.32,37.85 29.59,37.85 28.45,36.7 28.45,34.93 28.57,34.8 28.57,33.66 U2.G10
  Top 0.152: R23.1 43.43,36.07 45.74,36.07 U3.18
N$81  (via drill 0.25)
  Top 0.127: U2.C8 26.16,27.43 v26.16,23.37 | v32.26,23.37 32.38,23.5 32.51,23.5 34.16,25.15 43.18,25.15 43.43,25.02 R31.2
  Top 0.152: R31.2 43.42,25.09 | 43.42,25.09 U4.5 | 43.42,25.09 43.41,25.09
  Route2 0.127: v26.16,23.37 v32.26,23.37
N$86
  Top 0.152: U4.19 R39.2
N$88
  Top 0.152: R38.1 44.17,19.58 44.17,19.59 U4.16
N$93
  Top 0.127: 43.43,35.56 38.1,35.56 36.2,37.47 29.72,37.47 28.7,36.45 28.7,35.18 28.96,34.93 29.59,34.93 29.84,34.67 29.84,33.66 U2.G11
  Top 0.152: U3.19 43.44,35.61 43.43,35.61 R23.2 43.43,35.56
N$95
  Top 0.127: 43.34,40.61 41.66,40.64 41.05,41.25 29.05,41.25 24.51,36.7 24.51,36.2 24.64,36.07 24.64,34.93 24.51,34.8
  Top 0.152: R19.2 43.33,40.62 43.34,40.61 U3.9 | U2.H6 24.51,34.8
N$99
  Top 0.127: 25.4,35.61 25.53,35.74 25.53,36.45 29.34,40.26 40.13,40.26 40.77,39.62 R20.2
  Top 0.152: 44.13,39.61 44.15,39.62 R20.2 | 44.13,39.61 U3.11 | 44.13,39.61 44.12,39.6 | U2.J7 25.4,35.61
N$100
  Top 0.127: U2.G9 27.3,33.66 26.42,33.66 26.16,33.91 26.16,36.07 29.34,39.24 37.97,39.24 39.62,37.59 43.31,37.59 43.33,37.62 R21.2
  Top 0.152: 43.41,37.62 43.38,37.64 | R21.2 43.41,37.62 | U3.15 43.41,37.61 43.41,37.62
N$101
  Top 0.127: U2.J6 24.13,36.83 28.83,41.66 41.15,41.66 41.66,41.15 43.43,41.15
  Top 0.152: U3.8 43.45,41.11 R19.1 43.43,41.15 43.43,41.02
N$105  (via drill 0.25)
  Top 0.127: U2.D9 27.18,28.45 27.18,23.24 v26.8,22.86 | v31.75,22.86 32.89,22.86 33.27,23.24 37.34,23.24 38.48,24.38 43.94,24.38 44.07,24.51 44.2,24.51 R32.1
  Top 0.152: 44.1,24.59 44.12,24.56 R32.1 | 44.1,24.59 U4.6 | 44.1,24.59 44.09,24.59
  Route2 0.127: v26.8,22.86 v31.75,22.86
N$106  (via drill 0.25)
  Top 0.127: U2.C9 27.43,27.43 v27.43,22.35 | v32.26,22.35 32.77,22.35 33.4,22.99 37.47,22.99 38.61,24.13 43.94,24.13 44.07,24 44.12,24.05 R32.2
  Top 0.152: U4.7 44.23,24.09 R32.2
  Route2 0.127: v27.43,22.35 v32.26,22.35
N$107  (via drill 0.25)
  Top 0.127: U2.B9 28.57,26.04 v28.57,21.84 | v32.77,21.84 37.08,21.84 38.74,23.5 43.23,23.5 43.36,23.62
  Top 0.152: U4.8 43.5,23.59 43.49,23.57 43.46,23.6 R33.1 43.33,23.6 43.36,23.62
  Route2 0.152: v28.57,21.84 v32.77,21.84
N$108  (via drill 0.25)
  Top 0.127: v27.94,21.34 U2.A9 | v32.26,21.34 32.94,21.34 33.2,21.59 37.21,21.59 38.86,23.24 43.18,23.22 43.31,23.09
  Top 0.152: 43.38,23.09 43.36,23.11 | 43.38,23.09 R33.2 43.31,23.09 | U4.9 43.39,23.09 43.38,23.09
  Route2 0.152: v27.94,21.34 v32.26,21.34
N$109  (via drill 0.25)
  Top 0.127: U2.C10 29.72,28.45 38.48,28.45 39.12,27.81 39.12,27.05 v38.86,26.8 | R34.2 44.2,22.1 v38.99,22.1
  Top 0.152: 44.11,22.09 44.12,22.07 R34.2 | 44.11,22.09 U4.11 | 44.11,22.09 44.09,22.1
  Route2 0.127: v38.86,26.8 38.86,22.22 v38.99,22.1
N$114
  Top 0.152: 44.14,19.09 44.15,19.07 R38.2 | 44.14,19.09 U4.17 | 44.14,19.09 44.09,19.13
N$124
  Top 0.152: 44.2,17.09 44.17,17.12 | R40.2 44.2,17.09 | U4.21 44.2,17.09
N$126
  Top 0.152: R39.1 43.43,18.57 43.45,18.59 U4.18
N$131
  Top 0.152: R40.1 44.17,17.58 44.18,17.59 U4.20
OEL  (via drill 0.25)
  Top 0.127: U2.C11 29.84,27.3 29.84,26.42 30.23,26.04 30.73,26.04 30.99,25.78 30.99,21.46 v30.23,20.7 | v30.23,19.05 30.23,16.64 29.97,16.38 26.04,16.38 25.91,16.26 25.91,14.35 26.92,13.33 J3.3
  Bottom 0.127: v30.23,19.05 v30.23,20.7
OUT-ENABLE  (via drill 0.38)
  Top 0.203: U4.13 44.57,21.09 v44.32,21.34 | U3.13 44.57,38.61 v44.32,38.86
  Bottom 0.203: J1.99 60.16,8.34 59.94,8.13 54.74,8.13 54.61,8.26 SJ1.2 R24.2 52.01,17.08 48.01,21.08 45.85,21.08 45.59,21.34 | 45.59,21.34 v44.32,21.34 | 45.59,21.34 45.85,21.59 45.85,38.35 45.34,38.86 v44.32,38.86
OVDD  (via drill 0.25, 0.3)
  Top 0.254: v24.77,28.57 U2.D7
  Top 0.61: U2.H11 v31.11,33.66 U2.G12 v32.38,33.02 | v27.3,34.93 U2.H9
  Route2 0.305: v27.3,34.93 27.3,32.77 26.67,32.13 26.67,31.37 27.18,30.86 27.18,30.35 26.67,29.84 25.78,29.84 25.4,29.46 U2.D7 v24.77,28.57
  Bottom 0.61: v27.3,34.93 30.86,34.93 30.86,33.91 v31.11,33.66 U2.G12 v32.38,33.02
  Bottom 0.813: 30.86,34.93 R14.2
PWR-ON
  Bottom 0.203: J1.97 60.19,9.14 59.69,8.64 57.4,8.64 57.28,8.76 SJ1.1 53.72,8.76 53.21,9.27 R29.1
RF
  Top 0.406: 16.21,32.97 C42.1 | L1.2 15.58,32.96 15.57,32.97
  Top 0.508: C42.1 16.31,33.02 U2.G1 | 15.57,32.97 16.21,32.97
SCL
  Bottom 0.152: U1.6 59.25,12.52 59.56,12.83 61.98,12.83 62.23,12.57 62.87,12.57 62.8,12.51 R25.1 63.95,12.51 64.52,13.08 67.82,13.08 67.94,13.21 68.01,13.14 J1.87
SDA
  Bottom 0.152: U1.5 61.47,11.94 R26.1 61.47,12.06 64.01,12.06 64.64,11.43 67.82,11.43 67.82,11.56 67.83,11.54 J1.91
SENSE
  Top 0.127: 22.22,23.11 23.5,24.38 23.5,32.13 23.75,32.38 24.51,32.38 24.89,32.77 25.27,32.77 U2.G7
  Top 0.152: 22.22,23.11 22.22,16.89 21.72,16.38 16.26,16.38 16.03,16.15 16.03,15.39 15.98,15.34 J4.2
  Top 0.203: J4.4 16,13.33 15.99,13.32 J4.6
  Bottom 0.203: J4.2 15.98,15.34 15.98,13.36 16,13.33 J4.4
  Bottom 0.254: C19.1 17.53,11.3 17.49,11.33 J4.6
SHDN  (via drill 0.25)
  Top 0.127: U2.B11 31.24,25.91 31.24,20.83 v31.11,20.7 | v31.11,19.05 30.61,18.54 30.61,16.51 29.97,15.88 29.97,14.35 28.96,13.33 J3.4
  Bottom 0.127: v31.11,19.05 v31.11,20.7
VCC1  (via drill 0.3, 0.81)
  Top 0.152: U2.E1 v17.14,30.48 15.98,29.32 15.98,19.45 15.98,19.46 15.6,19.07 5.89,19.07 5.66,18.85 5.66,16.16 J6.1
  Top 0.406: U2.F2 v19.05,31.11 U2.E2 v18.41,30.48 U2.E1 v17.14,30.48
  Bottom 0.203: 34.86,48.83 R15.2 | R15.2 34.86,48.83 | 34.86,48.83 34.8,48.77
  Bottom 0.406: U2.E2 23.5,30.48
  Bottom 0.508: v17.14,30.48 v18.41,30.48 U2.E2 v19.05,31.11 | 23.5,30.48 23.88,30.86 23.88,35.94 26.04,38.1 26.04,39.24 27.43,40.64 32.64,40.64 33.27,41.28 v33.27,45.59 34.93,47.24 34.93,49.02 R15.2
VCC2  (via drill 0.3, 0.81)
  Top 0.152: R36.2 14.91,17.4 16.36,18.85 16.38,26.36 16.69,26.67 v17.14,26.67
  Top 0.406: U2.B2 v18.41,26.67 U2.B1 v17.14,26.67
  Bottom 0.406: v17.14,26.67 v18.41,26.67 19.56,26.67 19.68,26.54 19.68,24.13 19.81,24 23.24,24 23.5,24.26 23.5,28.57 24.13,29.21 25.15,29.21 25.4,29.46 25.4,30.23 25.27,30.35 25.27,30.73 25.4,30.86 25.4,31.37 25.27,31.5 25.27,32.77
  Bottom 0.508: 25.27,32.77 25.53,33.02 25.53,36.07 26.8,37.34 26.8,38.86 27.69,39.75 37.34,39.75 38.48,40.89 v38.48,45.59 R3.2 38.48,47.5
VCM
  Bottom 0.254: R11.1 R7.2 23.68,12.81 arc-90 23.67,12.83 arc-90 23.52,12.67 22.94,12.67 22.61,12.34 14.96,12.34 13.99,13.32 J4.3
VDD  (via drill 0.3, 0.81)
  Top 0.254: J4.1 14.86,14.35 17.4,14.35 18.41,15.37 19.94,15.37 | J3.2 J3.1 27.94,15.33 27.94,12.7 27.56,12.32 21.46,12.32 20.95,12.83 20.95,14.35 19.94,15.37 | 19.94,15.37 19.95,15.35 J2.1
  Top 0.305: U2.D11 29.84,29.84 27.3,29.84 U2.E8
  Top 0.406: v26.04,30.48 v26.04,29.84
  Top 0.61: U2.E7 v26.04,30.48 U2.E8
  Bottom 0.152: 26.92,15.33 26.92,15.24 | J3.1 26.92,15.33 | 26.92,15.33 26.92,15.37
  Bottom 0.254: R6.1 20.2,17.03 19.95,16.78 J2.1
  Bottom 0.305: v24.77,20.32 24.77,18.8 26.92,16.64 26.92,15.37
  Bottom 0.356: v24.77,20.32 24.77,27.3
  Bottom 0.406: 26.54,32.89 26.67,32.64 26.67,31.11 v26.04,30.48 26.04,28.57 24.77,27.3
  Bottom 0.61: 26.54,32.89 26.54,35.69 27.56,36.7 27.62,36.77 R13.2
VROM
  Bottom 0.152: J1.93 64.32,10.74 63.5,11.56 62.74,11.56 | 62.74,11.56 R25.2 | R26.2 61.66,11.11 62.1,11.56 62.74,11.56
  Bottom 0.254: 56.39,12.06 57.95,12.06 U1.8 57.95,11.6 57.53,11.18 57.53,9.4 57.66,9.27 59.44,9.27 59.56,9.4 59.56,10.79 59.69,10.92 61.21,10.92 61.47,11.18 R26.2 | C27.1 55.25,12.06 56.39,12.06 | R27.2 56.39,12.06

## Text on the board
Top: 4
Route2: 5
Route3: 6
Bottom: 7
tPlace: 2
bPlace: 9
tNames: +3.3V | +5V | GND | LO | DC1437B LTM9003IV- | +2.5V | PRE-DISTORTION RECEIVER | [LVDS OUTPUT] | www.linear.com | (408) 432-1900 | RF | AMP_EN | MIXER_EN | SENSE | MODE | OE# | SHDN | VDD | ON | ON | 2/3 | 1.25V | VDD | OFF | OFF | ON | ON | OFF | EXT | OFF | GND | 1/3 | EXT | GND | ENCODE | CLK | REF
bNames: LTC CONFIDENTIAL | FOR CUSTOMER USE ONLY | VCC1 | VCC2 | VDD
tStop: 3
bStop: 8
tCream: 1
bCream: 10
bRestrict: BACK | REV A2
Measures: 0.350 | NO TABS HERE | FIDUCIAL, 3X | 2.075 | 2.100 | 2.100 | NO TABS HERE | 2.300 | 0.050 | 0.100 | 0 | ORIGIN | 2.075 | NO TABS HERE | 1.100 | 0.067" TOOLING HOLE | 0.050 | UNPLATED, 2X | 0 | 2.760
Document: DC1437 | LM9003 PRE-DISTORTION RCVR | B | 10 | E.TRELEWICZ | 21JUL08
Reference: A2 | INITIAL RELEASE | 21JUL08 | 1 | 0.009" | 1 | 0.039" | 1 | 0.009" | 1 | DC1437 | REV B | DRILL LEGEND | SYM SIZE QTY TOLERANCE PLTD | .010 | 33 | +0/-.010 | YES | .012 | 545 | +0/- .012 | YES | .015 | 540 | +/- .003 | YES | .032 | 32 | +/- .003 | YES | LTM9003 | E.TRELEWICZ | .066 | 5 | +/- .003 | YES | .067 | 2 | +.004/-0 | NO | PRE-DISTORTION RECEIVER, LVDS OUTPUT | E.TRELEWICZ | E.TRELEWICZ | .188 | 4 | +/- .003 | YES | DC1437 | B | 1 | 1
tDocu: DC1437 | LM9003 PRE-DISTORTION RCVR | B | E.TRELEWICZ | 7AUG09
bDocu: DC1437 | B | LM9003 PRE-DISTORTION RCVR | E.TRELEWICZ | 7AUG09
